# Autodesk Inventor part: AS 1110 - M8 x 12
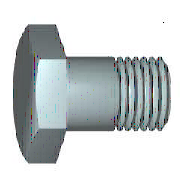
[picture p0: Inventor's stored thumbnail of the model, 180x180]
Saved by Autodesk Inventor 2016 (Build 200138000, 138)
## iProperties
IsCustomPart: 0
Created: 2015-02
Part Number: AS 1110 - M8 x 12
Material: Steel, Mild
Description: ISO metric hexagon precision bolts and screws
Document SubType Name: Modeling
Standard: AS 1110
Designer: stank
Standards Organization: AS
Language: en-US
Size Designation: M8 x 12
Categories: <MemberInstance><Categories><Category DisplayName="Fasteners" InternalName="e4da775c-781d-43d5-af7c-5136215cf5a6" Mnemonic="FSTN"><Category DisplayName="Bolts"
Density: 7.85 g/cm^3
Appearance: Semi-Polished
Mass: 10.6871 g
Surface Area: 8.11559 cm^2
Volume: 1.36142 cm^3
Author: stank
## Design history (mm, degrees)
sketch "Sketch1"
  geometry: L1 (0, 6.5)-(0, 4); L2 (3.7, 4)-(12, 4); L3 (12, 4)-(12, 0); L4 (12, 0)-(-0.6, 0); L5 (-0.7, 0)-(2.45, 0) reference; L6 (-0.6, 0)-(-0.6, 6.5); L7 (-0.6, 6.5)-(0, 6.5); L8 (3.7, 4)-(2.933, 4); L9 (2.933, 4)-(0, 4); L10 (0, -0.227)-(0, 1.362) reference
  constraints: 16 end point, 2 collinear, 2 perpendicular, 1 parallel
  dimensions: "d0" = 12 distance between parallel lines of L3 L1 (= NLG); "d1" = 8.3 distance from line of L2.start L3 (= GEL); "d2" = 8 diameter of L2 L4 (= GD); "d9" = 0.6001 distance between parallel lines of L6 L1 (computed from SD); "d10" = 13 diameter of L7 L4 (= SD2); "d13" = 0.76691 distance of L2.start L8.end (computed from GAL); "d14" = 8 diameter of L9 L4 (= BDM)
revolve "Body" sketch "Sketch1" stored, may be unused: angle "d12" = 90 deg
sketch "Sketch2"
  geometry: L1 (0, 7.506)-(6.5, 3.753); L2 (6.5, 3.753)-(6.5, -3.753); L3 (6.5, -3.753)-(0, -7.506); L4 (0, -7.506)-(-6.5, -3.753); L5 (-6.5, -3.753)-(-6.5, 3.753); L6 (-6.5, 3.753)-(0, 7.506); 2 further points
  constraints: 12 end point, 1 coincident, 1 vertical, 11 other
  dimensions: "d11" = 13 distance between parallel lines of L5 L2 (= SW)
extrude "Head" join sketch "Sketch2" distance "d3" = 4.7 (= KOH - SD); taper "d4" = 0 deg
sketch "Sketch4"
  geometry: L1 (-5.3, 6.5)-(-5.3, 7.506); L2 (-5.3, 7.506)-(-4.72, 7.506); L3 (-4.72, 7.506)-(-5.3, 6.5); L4 (-1.27, 0)-(-0.08, 0) reference; L5 (-0.6, 7.506)-(-5.3, 7.506) reference; L6 (-5.3, 3.753)-(-5.3, 7.506) reference
  constraints: 6 end point, 2 collinear, 1 perpendicular, 1 vertical
  dimensions: "d5" = 30 deg angle of L3 L1 (= ANG1); "d19" = 13 diameter of L1.start L4 (= SW0)
revolve "Chamfer1" sketch "Sketch4" stored, may be unused: angle "d21" = 90 deg
workplane "Work Plane1"
body "Solid1"
feature "Thread" dims "d15" = 8.3 (= GEL), "d16" = 0
chamfer "Chamfer2" distance "d6" = 0.76681 (= -0.5 x SPD + 0.5 x GD); stored, may be unused: second distance "d7" = 0.76691 (computed from GUL), angle "d55" = 45 deg
other parameters: "NLG" = 12 [user parameter; used in 1 equation term], "GD" = 8 (= NND) [user parameter; used in 2 equation terms], "BDM" = 8 (= NND) [user parameter; used in 1 equation term], "KOH" = 5.3 [user parameter; used in 1 equation term], "GEL" = 8.3 [user parameter; used in 2 equation terms], "SW" = 13 [user parameter; used in 5 equation terms], "SW0" = 13 (= SW) [user parameter; used in 1 equation term], "SPD" = 6.46637 (= NND - 1.2269 x PTC) [user parameter; used in 1 equation term], "SD2" = 13 (= SW) [user parameter; used in 1 equation term], "SD" = 0.6 [user parameter; used in 3 equation terms], "ANG1" = 30 deg [user parameter; used in 1 equation term], "GAL" = 0.76681 (= 0.61345 x PTC) [user parameter; used in 1 equation term], "GUL" = 0.76681 (= 0.61345 x PTC) [user parameter; used in 1 equation term], "d8" = 0, "RR" = 0.4 [user parameter], "d57" = 0, "d58" = 0, "TPU" = 8 (computed from PTC) [user parameter], "WFT" = 0.6 (= SD) [user parameter], "GD1" = 6.46637 (= THREADDIA - 1.2269 x PTC) [user parameter], "THREADDIA" = 8 [user parameter; used in 1 equation term], "SDH" = 13 (= SW) [user parameter], "TOA" = 30 deg [user parameter], "FAWI" = 45 deg [user parameter], "PTC" = 1.25 [user parameter; used in 5 equation terms], "NND" = 8 [user parameter; used in 3 equation terms], "E0" = 15.015 (= 1.155 x SW) [user parameter]
